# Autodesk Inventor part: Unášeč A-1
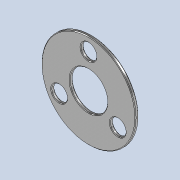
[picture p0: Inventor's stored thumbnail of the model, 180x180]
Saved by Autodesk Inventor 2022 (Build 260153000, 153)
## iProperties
Created: 2025-05
Part Number: Unášeč A-1
Material: Všeobecné
Document SubType Name: Modeling
Designer: jbart
Density: 1 g/cm^3
Appearance: Broušená
Mass: 527.643 g
Surface Area: 1207.14 cm^2
Volume: 527.643 cm^3
Author: jbart
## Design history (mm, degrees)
sketch "Náčrt1"
  geometry: L1 (0, 108)-(93.531, -54); L2 (93.531, -54)-(-93.531, -54); L3 (-93.531, -54)-(0, 108); L4 (0, 108)-(0, 0); L5 (0, 0)-(93.531, -54); L6 (0, 0)-(-93.531, -54); C1 r 25 at (0, 108); C2 r 25 at (-93.531, -54); C3 r 25 at (93.531, -54); C4 r 150 at (0, 0); C5 r 60 at (0, 0); 1 further point
  constraints: 12 end point, 6 coincident, 5 centre point, 1 vertical, 7 other
  dimensions: "d0" = 108 distance of L4.end L1.end; "d1" = 50 diameter of C1; "d2" = 50 diameter of C2; "d3" = 50 diameter of C3; "d4" = 300 diameter of C4; "d7" = 120 diameter of C5
extrude "Vysunutí2" new body sketch "Náčrt1" distance "d8" = 10; taper "d9" = 0 deg
chamfer "Zkosení1" distance "d10" = 2; stored, may be unused: second distance "d11" = 2, angle "d12" = 45 deg
node "Těleso2"
